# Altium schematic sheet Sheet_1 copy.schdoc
size 194 x 96 mm
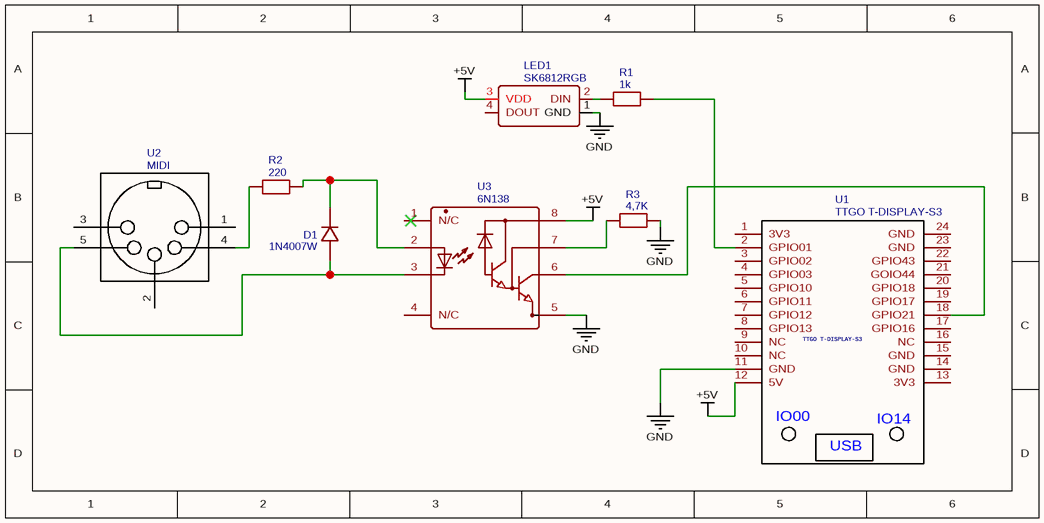
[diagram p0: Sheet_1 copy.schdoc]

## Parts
D1  1N4007W  [SOD-123_L2.8-W1.8-LS3.7-RD]
LED1  SK6812RGB  [LED-SMD_4P-L5.0-W5.0-TL-A_SK6812RGBW-NW]
R1  1k  [R1206-1]
R2  220  [R1206-1]
R3  4,7K  [R1206-1]
U1  TTGO T-DISPLAY-S3  [LILYGO T-DISPLAY-S3-V3]
U2  MIDI  [MIDI]
U3  6N138  [DIP-8_L9.8-W6.6-P2.54-LS7.6-BL]

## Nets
+5V: LED1.3(VDD) U1.12(5V) U3.8(VCC)
GND: LED1.1(GND) R3.2 U1.11(GND) U3.5(GND)
NetD1_1: D1.1 R2.2 U3.2(A)
NetD1_2: D1.2 U2.5 U3.3(C)
NetLED1_2: LED1.2(DIN) R1.1
NetR1_2: R1.2 U1.2(GPIO01)
NetR2_1: R2.1 U2.4
NetR3_1: R3.1 U3.7(VB)
NetU1_18: U1.18(GPIO21) U3.6(VOUT)

Not connected (* = marked no-connect by the designer): LED1 4(DOUT); U1 1(3V3) 3(GPIO02) 4(GPIO03) 5(GPIO10) 6(GPIO11) 7(GPIO12) 8(GPIO13) 9(NC) 10(NC) 13(3V3) 14(GND) 15(GND) 16(NC) 17(GPIO16) 19(GPIO17) 20(GPIO18) 21(GOIO44) 22(GPIO43) 23(GND) 24(GND); U2 1 2 3; U3 1(N/C) 4(N/C)

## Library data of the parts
D1 = 1N4007W: Manufacturer: BLUE ROCKET; Contributor: LCEDA_Lib
LED1 = SK6812RGB: Manufacturer: 欧思科光电; Manufacturer Part: SK6812RGBW-NW; Contributor: lcsc
R1 = 1k: nameAlias: Value(Ω); Contributor: LCEDA_Lib
R2 = 220: nameAlias: Value(Ω); Contributor: LCEDA_Lib
R3 = 4,7K: nameAlias: Value(Ω); Contributor: LCEDA_Lib
U1 = TTGO T-DISPLAY-S3: Manufacturer: lilygo; Contributor: hrituraj
U2 = MIDI: Contributor: snleal
U3 = 6N138: Manufacturer: ISOCOM(英国安数光); Contributor: LCSC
